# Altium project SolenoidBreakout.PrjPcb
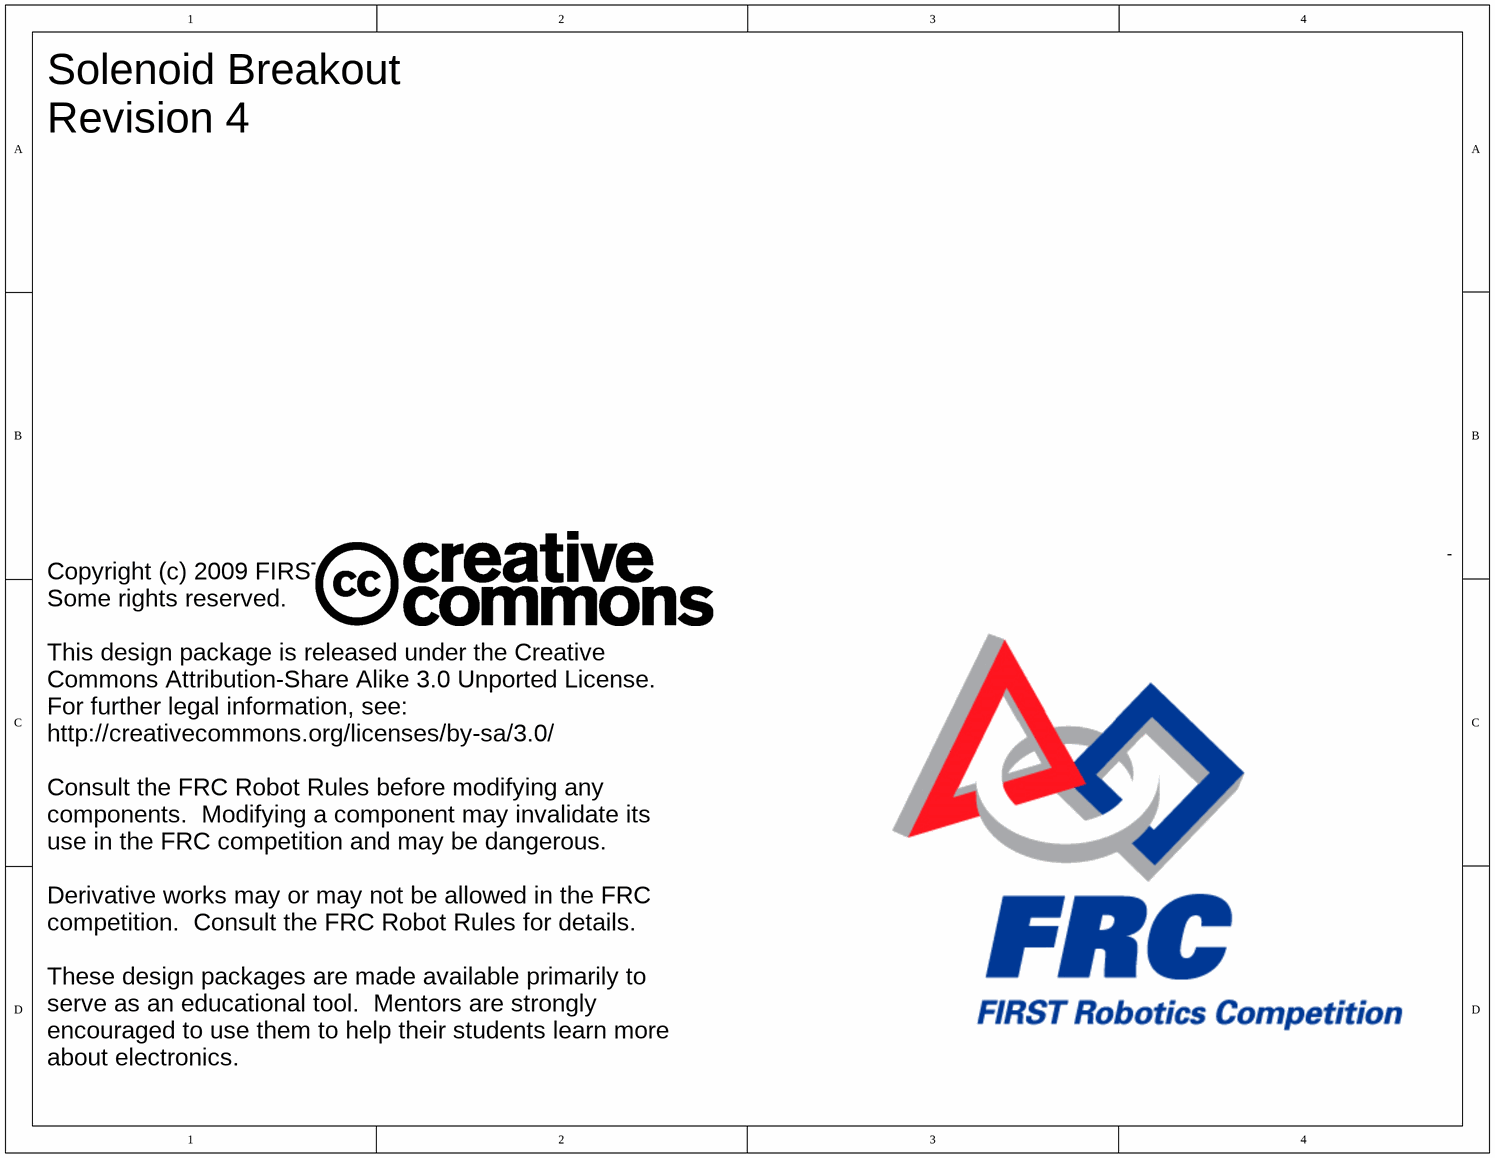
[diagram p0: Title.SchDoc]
ProjectTitle: Solenoid Breakout
2 sheets, 7 parts. Net scope: global (net labels, ports and power ports of the same name join across sheets).
Board file: SolenoidBreakout.PcbDoc
Sheets:
  Title.SchDoc
  SolenoidBreakout.SchDoc

## Sheet Title.SchDoc
size Letter; DocumentNumber: 1; SheetNumber: 1; SheetTotal: 2

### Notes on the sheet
- Solenoid Breakout
  Revision 4
- Copyright (c) 2009 FIRST
  Some rights reserved.
  This design package is released under the Creative Commons Attribution-Share Alike 3.0 Unported License.  For further legal information, see:
  http://creativecommons.org/licenses/by-sa/3.0/
  Consult the FRC Robot Rules before modifying any components.  Modifying a component may invalidate its use in the FRC competition and may be dangerous.
  Derivative works may or may not be allowed in the FRC competition.  Consult the FRC Robot Rules for details.
  These design packages are made available primarily to serve as an educational tool.  Mentors are strongly encouraged to use them to help their students learn more about electronics.

## Sheet SolenoidBreakout.SchDoc: Solenoid Breakout
size Letter; DrawnBy: EJVW; Engineer: EJVW; DocumentNumber: 2; Revision: 4; SheetNumber: 2; SheetTotal: 2
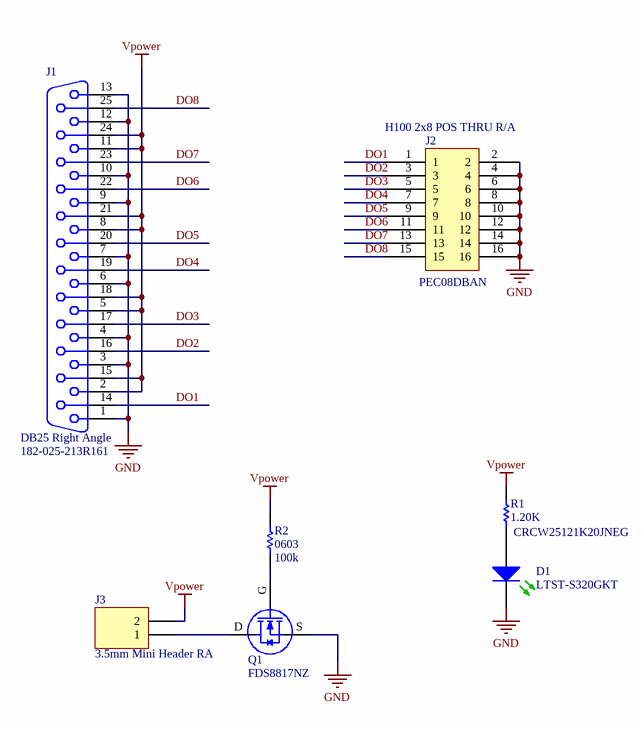
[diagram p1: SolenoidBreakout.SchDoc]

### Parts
D1  LTST-S320GKT  [LED1208RA LiteOn]
J1  DB25 Right Angle  MFG_PN: 182-025-213R161  [DB25 - RA]
J2  H100 2x8 POS THRU R/A  MFG_PN: PEC08DBAN  [H100P2x8RA]
J3  3.5mm Mini Header RA  [WAGO 734-162]
Q1  FDS8817NZ  [SO-8_M FET]
R1  value 1.20K  MFG_PN: CRCW25121K20JNEG  [R2512_C]  (hidden comment: 1.2k ohm 2512 5%)
R2  value 100k  Footprint: 0603  [R0603_C]  (hidden comment: 100k ohm 0603 1%)

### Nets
GND: D1.K J1.1 J1.3 J1.4 J1.6 J1.7 J1.9 J1.10 J1.12 J1.13 J2.2 J2.4 J2.6 J2.8 J2.10 J2.12 J2.14 J2.16 Q1.S
Vpower: J1.2 J1.5 J1.8 J1.11 J1.15 J1.18 J1.21 J1.24 J3.2 R1.2 R2.2
DO1: J1.14 J2.1
DO2: J1.16 J2.3
DO3: J1.17 J2.5
DO4: J1.19 J2.7
DO5: J1.20 J2.9
DO6: J1.22 J2.11
DO7: J1.23 J2.13
DO8: J1.25 J2.15
NetD1_A: D1.A R1.1
NetJ3_1: J3.1 Q1.D
NetQ1_G: Q1.G R2.1

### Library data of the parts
D1 = LTST-S320GKT: Green 1208RA 20mA 2V 10mcd; MFG: Panasonic - SSG; DIST: DigiKey; DIST_PN: 160-1206-1-ND; I_F: 20; Luminous Intensity: 12mcd; Maximum Continuous Current: 30; V_F: 2.1; Viewing Angle: 130; Cost (1000): 0.08000
J1 = DB25F RA Unthreaded: DB25F RA Unthreaded .318"; DIST: DigiKey; DIST_PN: 182-725FE-ND; MFG: Norcomp Inc.; BOM Note: Or Equivalent
J2 = H100 2x8 POS THRU VERT: DIST: DigiKey; DIST_PN: S2112E-08-ND; MFG: Sullins Electronics Corp.
J3 = WAGO 734-162: 3.5mm Header Protected against Mismating; MFG: WAGO; Current Rating: 10 A; Mates With: 734-102/037-000
Q1 = FDS8817NZ: N-CH 30V 8SOIC, ESD Protected; MFG: Fairchild Semiconductor; DIST: DigiKey; DIST_PN: FDS8817NZCT-ND; R_DS: 5.4mOhms; V_DS: 30; V_GS: 20; R?JC: 25; Topology: N; Q_G (nC): 45; V_THRESH (Volts): 1.0 - 1.8 - 3.0; Cost (1000): 0.34913; Cost (MOQ): 0.79; I_D Continuous: 15
R1 = 1.2k ohm 2512 5%: MFG: Vishay/Dale; DIST: DigiKey; DIST_PN: 541-1.2KXCT-ND; Power: 1W; Cost (1000): 0.08410
R2 = 100k ohm 0603 1%: MFG: Rohm; MFG_PN: MCR03EZPFX1003; DIST: DigiKey; DIST_PN: RHM100KHCT-ND; Power: 0.1; Cost (1000): 0.01595; Cost (MOQ): 0.076; BOM Note: Generic - May be replaced by equal or better part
